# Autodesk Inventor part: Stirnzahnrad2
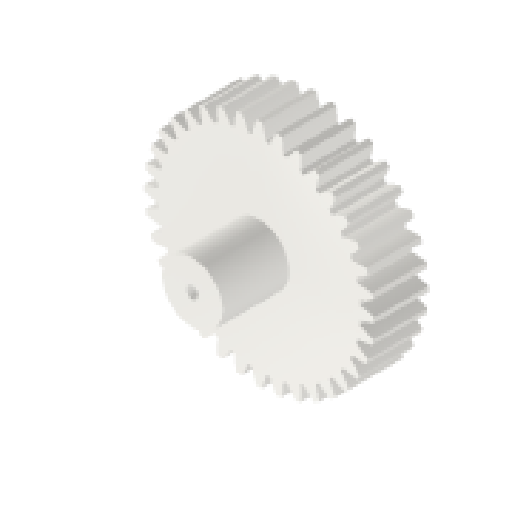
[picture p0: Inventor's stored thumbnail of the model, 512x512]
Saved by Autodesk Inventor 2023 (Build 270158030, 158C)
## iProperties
CustomPartVersion: 1
Created: 2022-09
Part Number: Stirnzahnrad2
Material: Steel
Document SubType Name: Modeling
Designer: Christoph Steinmann
Categories: <?xml version="1.0" encoding="UTF-16"?> <MemberInstance><Categories><FamilyTemplate><FamilyTemplateParameter ValueType="xs:double" Id="1" ObjectReferenceKey="da
Density: 1 g/cm^3
Appearance: Steel
Author: Christoph Steinmann
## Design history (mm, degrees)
sketch "Sketch1"
  geometry: C1 r 38 at (0, 0)
  constraints: 1 centre point
  dimensions: "d0" = 76 diameter of C1 (= da_da)
extrude "Extrusion1" new body sketch "Sketch1" distance "d1" = 20 (= da_b); taper "d2" = 0 deg
workplane "Work Plane2"
sketch "Sketch2"
  geometry: C1 r 38 at (0, 0) reference; C2 r 36 at (0, 0)
  constraints: 1 centre point, 1 coincident
  dimensions: "d3" = 72 diameter of C2 (= da_d)
feature "Flankendurchmesser" sketch "Sketch2" dims "d4" = 10, "d5" = 0
workplane "Work Plane8"
workplane "Work Plane9"
feature "Stirnzahnrad" dims "da_b" = 20, "da_d" = 72, "da_aw" = 60, "da_da" = 76, "da_df" = 67, "da_dw" = 72, angle "da_beta" = 0 deg, "da_lefttooth" = 0, "da_righttooth" = 0
sketch "Skizze3"
  geometry: C1 r 10 at (0, 0); 1 further point
  constraints: 1 centre point, 1 coincident
  dimensions: "d49" = 20 diameter of C1
extrude "Extrusion2" join sketch "Skizze3" distance "d50" = 22; taper "d51" = 0 deg
sketch "Skizze4"
  geometry: C1 r 10 at (0, 0) reference; A1 r 21.494 centre (16.154, 31.219) between (30.045, 14.817) and (33.316, 18.278) reference; 2 further points
  constraints: 1 coincident, 3 other
extrude "Extrusion3" cut sketch "Skizze4" distance "d52" = 2; taper "d53" = 0 deg
sketch "Skizze5"
  geometry: C1 r 2 at (0, 0); 1 further point
  constraints: 1 centre point, 1 coincident
  dimensions: "d54" = 4 diameter of C1
extrude "Extrusion4" cut sketch "Skizze5" extent not by distance; stored distance "d55" = 0; taper "d56" = 0 deg
body "Solid1"
body "Srf1"
other parameters: "d17" = 0, "d34" = 5 deg (computed from da_z), "d39" = 0, "d41" = 0, "d47" = 0, "d48" = 0
